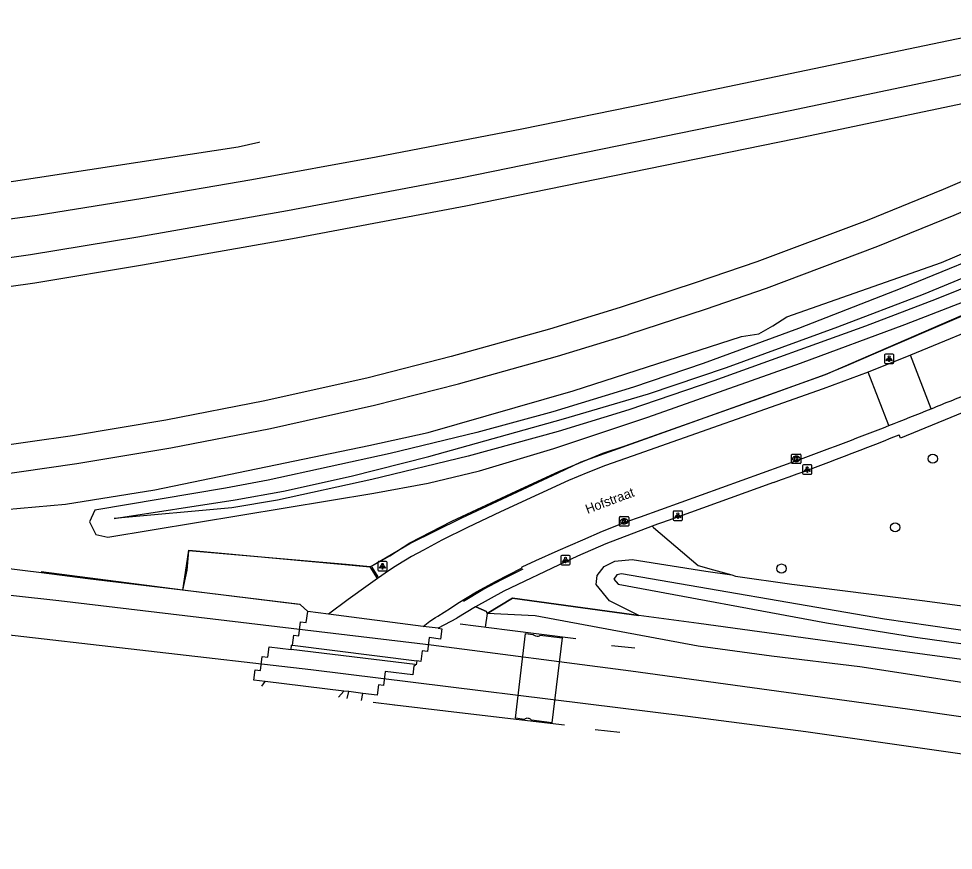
# Model space of a CAD drawing. Extents: x 162990 to 165007, y 383433 to 384336.
# Drawn here: x 163237.1 to 163336.6, y 383947.4 to 384036 of the extents above; entities that cross this region are included whole.
import ezdxf

# ---------------------------------------------------------------- set-up
doc = ezdxf.new("R2010")
doc.units = 0
for name, color, linetype in [('IMGEO_Berm_groen', 7, 'Continuous'), ('IMGEO_Boom', 7, 'Continuous'), ('IMGEO_Grasland_overig', 7, 'Continuous'), ('IMGEO_Greppel_droge_sloot', 7, 'Continuous'), ('IMGEO_Groenvoorziening', 7, 'Continuous'), ('IMGEO_Hek', 7, 'Continuous'), ('IMGEO_Kolk', 7, 'Continuous'), ('IMGEO_Lichtpunt', 7, 'Continuous'), ('IMGEO_Openbare_ruimte_label', 7, 'Continuous'), ('IMGEO_Overweg_gesloten', 7, 'Continuous'), ('IMGEO_Rijbaan_lokaal_open', 7, 'Continuous'), ('IMGEO_Spoor', 7, 'Continuous'), ('IMGEO_Spoorbaan_gesloten', 7, 'Continuous'), ('IMGEO_Spoorbaan_halfverhard', 7, 'Continuous'), ('IMGEO_Voetpad_open', 7, 'Continuous')]:
    doc.layers.add(name, color=color, linetype=linetype)

msp = doc.modelspace()

# ---------------------------------------------------------------- linework, layer by layer
at = {"layer": 'IMGEO_Berm_groen'}
msp.add_lwpolyline([(163274.504, 383977.632), (163278.725, 383980.117), (163284.265, 383982.864), (163294.54, 383987.657), (163296.984, 383988.804), (163323.041, 383998.108), (163383.183, 384024.211), (163402.575, 384035.786), (163402.671, 384035.843), (163402.812, 384035.885), (163403.247, 384036.139), (163416.877, 384040.507), (163432.67, 384043.744)], dxfattribs=at)
at = {"layer": 'IMGEO_Boom'}
for centre in [(163334.456, 383989.158), (163330.444, 383981.843), (163318.336, 383977.453)]:
    msp.add_circle(centre, 0.489, dxfattribs=at)
at = {"layer": 'IMGEO_Grasland_overig'}
for points in [[(163342.972, 384012.156), (163331.165, 384007.304), (163320.164, 384003.038), (163309.979, 383999.286), (163302.567, 383996.776), (163293.987, 383994.145), (163285.879, 383991.937), (163276.631, 383989.703), (163263.65, 383986.875), (163259.094, 383986.022), (163245.152, 383983.669)], [(163245.152, 383983.669), (163244.587, 383982.445), (163245.283, 383981.092), (163246.57, 383980.794), (163274.912, 383985.473), (163280.669, 383986.55), (163286.157, 383987.877), (163294.069, 383990.254), (163304.088, 383993.574), (163320.354, 383999.335), (163331.466, 384003.436), (163338.904, 384006.333)], [(163304.538, 383981.977), (163304.708, 383981.835), (163309.473, 383977.765), (163311.103, 383977.312), (163313.037, 383976.774)], [(163303.12, 383972.457), (163300.026, 383974.011), (163298.586, 383975.747), (163298.705, 383976.708), (163299.453, 383977.67), (163300.569, 383978.245), (163302.435, 383978.402), (163310.274, 383977.162), (163313.037, 383976.774)], [(163286.956, 383972.666), (163289.676, 383974.314), (163297.159, 383973.255), (163303.12, 383972.457)], [(163387.544, 383960.538), (163366.442, 383963.654), (163364.063, 383964.046), (163356.548, 383965.123), (163349.156, 383966.209), (163331.773, 383968.554), (163309.512, 383971.604), (163303.12, 383972.457)]]:
    msp.add_lwpolyline(points, dxfattribs=at)
at = {"layer": 'IMGEO_Greppel_droge_sloot'}
for points in [[(163274.685, 383986.922), (163264.631, 383984.748), (163259.777, 383983.906), (163247.226, 383982.795), (163260.11, 383984.784), (163265.254, 383985.705), (163272.493, 383987.277), (163280.746, 383989.392), (163295.118, 383993.387), (163304.152, 383996.079), (163312.467, 383998.865), (163324.349, 384003.186), (163333.485, 384006.672), (163348.011, 384012.683)], [(163341.944, 384009.015), (163334.832, 384006.165), (163327.28, 384003.289), (163311.133, 383997.456), (163302.073, 383994.345), (163294.531, 383992.039), (163284.935, 383989.436), (163274.685, 383986.922)], [(163409.986, 383960.583), (163388.793, 383964.228), (163377.195, 383965.699), (163360.31, 383968.096), (163346.455, 383969.572), (163329.328, 383972.064), (163301.28, 383976.885), (163300.783, 383976.774), (163300.462, 383976.334), (163300.94, 383975.775), (163323.14, 383971.677), (163332.603, 383970.136), (163384.444, 383962.888), (163409.693, 383958.969)]]:
    msp.add_lwpolyline(points, dxfattribs=at)
at = {"layer": 'IMGEO_Groenvoorziening'}
msp.add_lwpolyline([(163313.037, 383976.774), (163313.451, 383976.659), (163319.434, 383975.788), (163333.339, 383974.06), (163338.947, 383973.319)], dxfattribs=at)
at = {"layer": 'IMGEO_Hek'}
for points in [[(163254.527, 383975.145), (163255.168, 383979.396), (163274.504, 383977.632), (163274.644, 383977.711), (163276.585, 383978.805), (163278.717, 383980.181), (163283.214, 383982.499), (163290.073, 383985.701), (163294.599, 383987.803), (163297.161, 383988.847), (163299.287, 383989.75), (163301.676, 383990.541), (163315.913, 383995.57), (163322.989, 383998.132), (163325.305, 383999.08), (163329.992, 384001.097), (163341.559, 384006.06), (163350.753, 384010.132), (163366.939, 384017.167), (163383.117, 384024.211), (163402.701, 384035.889), (163408.952, 384037.884)], [(163266.956, 383973.642), (163254.527, 383975.145), (163239.451, 383977.111)], [(163274.669, 383977.596), (163275.328, 383976.57)], [(163284.454, 383973.989), (163286.526, 383975.221), (163288.599, 383976.341), (163290.806, 383977.414)], [(163297.159, 383973.255), (163289.676, 383974.314), (163286.956, 383972.666), (163286.758, 383971.22)], [(163285.777, 383973.367), (163286.892, 383972.867)], [(163387.33, 383959.283), (163387.544, 383960.538), (163366.442, 383963.654), (163364.063, 383964.046), (163356.548, 383965.123), (163349.156, 383966.209), (163331.773, 383968.554), (163309.512, 383971.604), (163303.12, 383972.457), (163297.159, 383973.255)], [(163284.096, 383971.554), (163289.091, 383970.927), (163296.413, 383969.999)], [(163300.233, 383969.246), (163302.725, 383969)], [(163274.829, 383963.207), (163277.133, 383962.938), (163285.218, 383961.992), (163295.21, 383960.806)], [(163277.133, 383962.938), (163277.124, 383962.872)], [(163298.477, 383960.317), (163301.101, 383960.028)]]:
    msp.add_lwpolyline(points, dxfattribs=at)
at = {"layer": 'IMGEO_Kolk'}
for p, q in [((163319.412, 383988.714), (163319.412, 383989.566)), ((163319.487, 383989.64), (163320.339, 383989.64)), ((163319.923, 383988.86), (163319.898, 383988.86)), ((163319.9, 383989.42), (163319.925, 383989.42)), ((163320.413, 383989.566), (163320.413, 383988.714)), ((163320.339, 383988.64), (163319.487, 383988.64)), ((163301.06, 383982.057), (163301.06, 383982.909)), ((163301.135, 383982.983), (163301.987, 383982.983)), ((163301.548, 383982.763), (163301.573, 383982.763)), ((163302.061, 383982.909), (163302.061, 383982.057)), ((163301.987, 383981.983), (163301.135, 383981.983)), ((163301.571, 383982.203), (163301.546, 383982.203))]:
    msp.add_line(p, q, dxfattribs=at)
for points in [[(163319.412, 383988.714), (163319.412, 383989.566)], [(163319.487, 383989.64), (163320.339, 383989.64)], [(163319.733, 383989.34), (163319.856, 383989.34), (163319.856, 383989.189), (163319.986, 383989.34), (163320.15, 383989.34), (163320.004, 383989.189), (163320.157, 383988.94), (163320.005, 383988.94), (163319.92, 383989.104), (163319.856, 383989.037), (163319.856, 383988.94), (163319.733, 383988.94), (163319.733, 383989.34)], [(163320.413, 383989.566), (163320.413, 383988.714)], [(163320.339, 383988.64), (163319.487, 383988.64)], [(163301.06, 383982.057), (163301.06, 383982.909)], [(163301.135, 383982.983), (163301.987, 383982.983)], [(163302.061, 383982.909), (163302.061, 383982.057)], [(163301.987, 383981.983), (163301.135, 383981.983)], [(163301.381, 383982.683), (163301.504, 383982.683), (163301.504, 383982.532), (163301.634, 383982.683), (163301.798, 383982.683), (163301.652, 383982.532), (163301.805, 383982.283), (163301.653, 383982.283), (163301.568, 383982.447), (163301.504, 383982.38), (163301.504, 383982.283), (163301.381, 383982.283), (163301.381, 383982.683)]]:
    msp.add_lwpolyline(points, dxfattribs=at)
for centre, start, end in [((163319.489, 383989.564), 91.55205, 178.44795), ((163319.489, 383989.564), 91.55205, 178.44795), ((163320.337, 383989.564), 1.55205, 88.44795), ((163320.337, 383989.564), 1.55205, 88.44795), ((163319.489, 383988.716), 181.55205, 268.44795), ((163319.489, 383988.716), 181.55205, 268.44795), ((163320.337, 383988.716), 271.55205, 358.44795), ((163320.337, 383988.716), 271.55205, 358.44795), ((163301.137, 383982.907), 91.55205, 178.44795), ((163301.137, 383982.907), 91.55205, 178.44795), ((163301.985, 383982.907), 1.55205, 88.44795), ((163301.985, 383982.907), 1.55205, 88.44795), ((163301.137, 383982.059), 181.55205, 268.44795), ((163301.137, 383982.059), 181.55205, 268.44795), ((163301.985, 383982.059), 271.55205, 358.44795), ((163301.985, 383982.059), 271.55205, 358.44795)]:
    msp.add_arc(centre, 0.0765, start, end, dxfattribs=at)
for centre, major_axis, ratio, start_param, end_param in [((163319.899, 383989.14), (-0.387, 0.002), 0.722429, 4.712389, 7.853982), ((163319.924, 383989.14), (-0.39, 0.002), 0.717154, 1.570796, 4.712389), ((163301.547, 383982.483), (-0.387, 0.002), 0.722429, 4.712389, 7.853982), ((163301.572, 383982.483), (-0.39, 0.002), 0.717154, 1.570796, 4.712389)]:
    msp.add_ellipse(centre, major_axis=major_axis, ratio=ratio, start_param=start_param, end_param=end_param, dxfattribs=at)
at = {"layer": 'IMGEO_Lichtpunt'}
for p, q in [((163329.308, 384000.202), (163329.308, 383999.395)), ((163329.308, 384000.202), (163329.308, 383999.395)), ((163330.21, 384000.297), (163329.402, 384000.297)), ((163330.21, 384000.297), (163329.402, 384000.297)), ((163330.304, 383999.395), (163330.304, 384000.202)), ((163330.304, 383999.395), (163330.304, 384000.202)), ((163329.402, 383999.301), (163330.21, 383999.301)), ((163329.402, 383999.301), (163330.21, 383999.301)), ((163320.582, 383988.407), (163320.582, 383987.6)), ((163320.582, 383988.407), (163320.582, 383987.6)), ((163321.484, 383988.502), (163320.676, 383988.502)), ((163321.484, 383988.502), (163320.676, 383988.502)), ((163321.578, 383987.6), (163321.578, 383988.407)), ((163321.578, 383987.6), (163321.578, 383988.407)), ((163320.676, 383987.506), (163321.484, 383987.506)), ((163320.676, 383987.506), (163321.484, 383987.506)), ((163306.797, 383983.488), (163306.797, 383982.681)), ((163306.797, 383983.488), (163306.797, 383982.681)), ((163307.699, 383983.583), (163306.891, 383983.583)), ((163307.699, 383983.583), (163306.891, 383983.583)), ((163307.793, 383982.681), (163307.793, 383983.488)), ((163307.793, 383982.681), (163307.793, 383983.488)), ((163306.891, 383982.587), (163307.699, 383982.587)), ((163306.891, 383982.587), (163307.699, 383982.587)), ((163295.727, 383978.851), (163294.919, 383978.851)), ((163295.727, 383978.851), (163294.919, 383978.851)), ((163275.317, 383978.111), (163275.317, 383977.304)), ((163275.317, 383978.111), (163275.317, 383977.304)), ((163276.219, 383978.206), (163275.411, 383978.206)), ((163276.219, 383978.206), (163275.411, 383978.206)), ((163276.313, 383977.304), (163276.313, 383978.111)), ((163276.313, 383977.304), (163276.313, 383978.111)), ((163294.825, 383978.756), (163294.825, 383977.949)), ((163294.825, 383978.756), (163294.825, 383977.949)), ((163294.919, 383977.855), (163295.727, 383977.855)), ((163294.919, 383977.855), (163295.727, 383977.855)), ((163295.821, 383977.949), (163295.821, 383978.756)), ((163295.821, 383977.949), (163295.821, 383978.756)), ((163275.411, 383977.21), (163276.219, 383977.21)), ((163275.411, 383977.21), (163276.219, 383977.21))]:
    msp.add_line(p, q, dxfattribs=at)
for points in [[(163329.682, 383999.866), (163329.721, 383999.838), (163329.533, 383999.576), (163329.495, 383999.603), (163329.682, 383999.866)], [(163329.784, 383999.818), (163329.831, 383999.818), (163329.831, 383999.496), (163329.784, 383999.496), (163329.784, 383999.818)], [(163329.894, 383999.838), (163329.932, 383999.865), (163330.119, 383999.603), (163330.08, 383999.575), (163329.894, 383999.838)], [(163320.956, 383988.071), (163320.995, 383988.043), (163320.807, 383987.781), (163320.769, 383987.808), (163320.956, 383988.071)], [(163321.058, 383988.023), (163321.105, 383988.023), (163321.105, 383987.701), (163321.058, 383987.701), (163321.058, 383988.023)], [(163321.168, 383988.043), (163321.206, 383988.07), (163321.393, 383987.808), (163321.354, 383987.78), (163321.168, 383988.043)], [(163307.171, 383983.152), (163307.21, 383983.124), (163307.022, 383982.862), (163306.984, 383982.889), (163307.171, 383983.152)], [(163307.273, 383983.104), (163307.32, 383983.104), (163307.32, 383982.782), (163307.273, 383982.782), (163307.273, 383983.104)], [(163307.383, 383983.124), (163307.421, 383983.151), (163307.608, 383982.889), (163307.569, 383982.861), (163307.383, 383983.124)], [(163275.691, 383977.775), (163275.73, 383977.747), (163275.542, 383977.485), (163275.504, 383977.512), (163275.691, 383977.775)], [(163275.903, 383977.747), (163275.941, 383977.774), (163276.128, 383977.512), (163276.089, 383977.484), (163275.903, 383977.747)], [(163295.199, 383978.42), (163295.238, 383978.392), (163295.05, 383978.13), (163295.012, 383978.157), (163295.199, 383978.42)], [(163295.301, 383978.372), (163295.348, 383978.372), (163295.348, 383978.05), (163295.301, 383978.05), (163295.301, 383978.372)], [(163295.411, 383978.392), (163295.449, 383978.419), (163295.636, 383978.157), (163295.597, 383978.129), (163295.411, 383978.392)], [(163275.793, 383977.727), (163275.84, 383977.727), (163275.84, 383977.405), (163275.793, 383977.405), (163275.793, 383977.727)]]:
    msp.add_lwpolyline(points, dxfattribs=at)
for centre in [(163329.807, 384000), (163321.081, 383988.205), (163307.296, 383983.286), (163275.816, 383977.909), (163295.324, 383978.554)]:
    msp.add_circle(centre, 0.0994, dxfattribs=at)
for centre, start, end in [((163329.402, 384000.202), 90, 180), ((163329.402, 384000.202), 90, 180), ((163330.21, 384000.202), 0, 90), ((163330.21, 384000.202), 0, 90), ((163329.402, 383999.395), 180, 270), ((163329.402, 383999.395), 180, 270), ((163330.21, 383999.395), 270, 0), ((163330.21, 383999.395), 270, 360), ((163320.676, 383988.407), 90, 180), ((163320.676, 383988.407), 90, 180), ((163321.484, 383988.407), 0, 90), ((163321.484, 383988.407), 0, 90), ((163320.676, 383987.6), 180, 270), ((163320.676, 383987.6), 180, 270), ((163321.484, 383987.6), 270, 0), ((163321.484, 383987.6), 270, 360), ((163306.891, 383983.488), 90, 180), ((163306.891, 383983.488), 90, 180), ((163307.699, 383983.488), 0, 90), ((163307.699, 383983.488), 0, 90), ((163306.891, 383982.681), 180, 270), ((163306.891, 383982.681), 180, 270), ((163307.699, 383982.681), 270, 0), ((163307.699, 383982.681), 270, 360), ((163294.919, 383978.756), 90, 180), ((163294.919, 383978.756), 90, 180), ((163295.727, 383978.756), 0, 90), ((163295.727, 383978.756), 0, 90), ((163275.411, 383978.111), 90, 180), ((163275.411, 383978.111), 90, 180), ((163276.219, 383978.111), 0, 90), ((163276.219, 383978.111), 0, 90), ((163294.919, 383977.949), 180, 270), ((163294.919, 383977.949), 180, 270), ((163295.727, 383977.949), 270, 0), ((163295.727, 383977.949), 270, 360), ((163275.411, 383977.304), 180, 270), ((163275.411, 383977.304), 180, 270), ((163276.219, 383977.304), 270, 0), ((163276.219, 383977.304), 270, 360)]:
    msp.add_arc(centre, 0.0946, start, end, dxfattribs=at)
at = {"layer": 'IMGEO_Overweg_gesloten'}
for points in [[(163266.223, 383969.281), (163266.357, 383970.366), (163266.911, 383970.298), (163267.095, 383971.787), (163267.702, 383971.712), (163267.85, 383972.865)], [(163270.07, 383972.581), (163267.85, 383972.865)], [(163280.155, 383971.294), (163270.07, 383972.581)], [(163281.743, 383971.091), (163282.132, 383971.041), (163281.998, 383969.948), (163280.806, 383970.095), (163280.623, 383968.607), (163280.034, 383968.679), (163279.896, 383967.556), (163279.464, 383967.61)], [(163281.743, 383971.091), (163280.155, 383971.294)], [(163263.311, 383965.418), (163262.124, 383965.562), (163262.256, 383966.656), (163262.824, 383966.588), (163263.003, 383968.077), (163263.598, 383968.006), (163263.732, 383969.12), (163266.077, 383968.834)], [(163279.299, 383967.218), (163266.077, 383968.834)], [(163266.223, 383969.281), (163279.464, 383967.61)], [(163279.299, 383967.218), (163279.283, 383967.091), (163279.176, 383967.104), (163279.061, 383966.15), (163276.121, 383966.503), (163275.942, 383965.014), (163275.381, 383965.081), (163275.247, 383963.975), (163273.715, 383964.16)], [(163271.683, 383964.406), (163263.311, 383965.418)], [(163272.219, 383964.341), (163271.683, 383964.406)], [(163273.715, 383964.16), (163272.219, 383964.341)]]:
    msp.add_lwpolyline(points, dxfattribs=at)
at = {"layer": 'IMGEO_Rijbaan_lokaal_open'}
for points in [[(163364.723, 384014.183), (163349.325, 384007.457), (163341.556, 384004.085), (163332.067, 384000.185)], [(163332.067, 384000.185), (163327.564, 383998.356)], [(163334.277, 383994.471), (163332.067, 384000.185)], [(163327.564, 383998.356), (163322.766, 383996.61), (163302.414, 383989.419), (163299.572, 383988.415), (163297.702, 383987.696), (163295.645, 383986.817), (163292.488, 383985.394), (163288.397, 383983.488), (163284.88, 383981.84), (163282.128, 383980.477), (163280.177, 383979.402), (163278.915, 383978.721), (163277.447, 383977.863), (163277.156, 383977.674), (163276.568, 383977.292), (163275.296, 383976.404)], [(163329.76, 383992.677), (163327.564, 383998.356)], [(163280.155, 383971.294), (163280.846, 383971.835), (163281.46, 383972.231), (163281.717, 383972.396), (163283.075, 383973.248), (163283.852, 383973.763), (163285.829, 383974.963), (163287.921, 383976.127), (163290.63, 383977.508), (163290.699, 383977.621), (163292.173, 383978.312), (163294.536, 383979.378), (163297.17, 383980.528), (163299.265, 383981.44), (163301.863, 383982.449), (163303.301, 383982.956), (163320.649, 383989.228)], [(163274.504, 383977.632), (163271.951, 383977.87), (163269.445, 383978.093), (163255.162, 383979.353), (163254.956, 383977.287), (163254.51, 383975.136)], [(163275.296, 383976.404), (163274.504, 383977.632)], [(163275.296, 383976.404), (163274.286, 383975.698), (163272.178, 383974.143), (163270.07, 383972.581)], [(163271.683, 383964.406), (163271.115, 383963.746)]]:
    msp.add_lwpolyline(points, dxfattribs=at)
for centre, radius, start, end in [((163168.64, 384405.397), 443.053, 291.95353, 292.59596), ((163164.319, 384415.815), 454.331, 291.35484, 291.96777), ((163165.37, 384413.176), 451.49, 290.11617, 291.35249)]:
    msp.add_arc(centre, radius, start, end, dxfattribs=at)
at = {"layer": 'IMGEO_Spoor'}
for points in [[(163482.504, 384064.124), (163438.347, 384055.003), (163304.284, 384027.02), (163290.651, 384024.258), (163275.14, 384021.273), (163261.909, 384018.846), (163250.276, 384016.868), (163239.034, 384015.076), (163225.051, 384013.191), (163210.675, 384011.424), (163197.565, 384010.035), (163186.306, 384009.051), (163170.778, 384007.955), (163157.742, 384007.242), (163145.353, 384006.773), (163136.4, 384006.585), (163127.534, 384006.532), (163114.97, 384006.669), (163093.304, 384007.27), (163079.785, 384007.903), (163066.124, 384008.71), (163050.352, 384009.854), (163020.285, 384012.339), (163007.925, 384013.445)], [(163407.712, 384044.788), (163319.259, 384026.2), (163284.13, 384019.05), (163265.686, 384015.557), (163249.751, 384012.76), (163238.315, 384010.853), (163218.995, 384008.118), (163175.893, 384003.972), (163154.95, 384002.739), (163133.868, 384002.083), (163105.006, 384002.112), (163077.274, 384002.797), (163012.331, 384005.282)], [(163408.318, 384042.866), (163400.768, 384040.461), (163393.355, 384037.964), (163386.355, 384035.481), (163379.622, 384032.97), (163369.229, 384028.838), (163351.977, 384021.599), (163336.715, 384015.07), (163328.559, 384011.745), (163316.709, 384007.296), (163310.206, 384005.061), (163302.041, 384002.4)], [(163171.029, 383983.535), (163183.994, 383983.622), (163194.126, 383983.904), (163202.816, 383984.295), (163211.591, 383984.954), (163223, 383986.029), (163234.105, 383987.344), (163243.254, 383988.629), (163253.264, 383990.312), (163263.9, 383992.378), (163274.976, 383994.865), (163283.901, 383997.126), (163294.45, 384000.073), (163302.041, 384002.4)], [(163201.068, 383978.5), (163241.346, 383974.044), (163280.995, 383969.314), (163302.293, 383966.549), (163331.756, 383962.529), (163375.788, 383956.21), (163396.784, 383952.981), (163406.788, 383951.295)], [(163233.552, 383970.681), (163268.173, 383966.7), (163308.347, 383961.743), (163320.922, 383960.101), (163364.427, 383953.887), (163378.978, 383951.698), (163406.172, 383947.444)]]:
    msp.add_lwpolyline(points, dxfattribs=at)
at = {"layer": 'IMGEO_Spoorbaan_gesloten'}
msp.add_lwpolyline([(163291.069, 383970.536), (163291.869, 383970.442), (163291.993, 383970.345), (163292.133, 383970.28), (163292.317, 383970.256), (163292.457, 383970.264), (163292.548, 383970.29), (163292.638, 383970.351), (163294.975, 383970.075), (163293.879, 383961.035), (163291.686, 383961.298), (163291.657, 383961.339), (163291.577, 383961.408), (163291.45, 383961.472), (163291.353, 383961.494), (163291.213, 383961.503), (163291.116, 383961.487), (163291.007, 383961.434), (163290.951, 383961.386), (163289.983, 383961.502), (163291.069, 383970.536)], dxfattribs=at)
at = {"layer": 'IMGEO_Spoorbaan_halfverhard'}
for points in [[(163230.824, 383983.328), (163242.036, 383984.311), (163251.576, 383985.84), (163274.361, 383990.577), (163280.675, 383991.959), (163296.124, 383996.4), (163314.071, 384002.164), (163315.928, 384002.462), (163317.416, 384003.302), (163318.906, 384004.275), (163335.392, 384010.064), (163360.951, 384020.902), (163385.565, 384031.616), (163387.408, 384031.711), (163388.822, 384032.318), (163390.428, 384033.418), (163407.515, 384038.818), (163419.45, 384042.131), (163441.356, 384047.511)], [(163219.349, 384005.138), (163238.772, 384007.888), (163250.257, 384009.803), (163266.224, 384012.606), (163284.708, 384016.106), (163319.867, 384023.262), (163376.601, 384035.185), (163350.807, 384024.361), (163335.559, 384017.838), (163327.465, 384014.539), (163315.694, 384010.119), (163309.254, 384007.906), (163301.137, 384005.261), (163293.607, 384002.952), (163283.129, 384000.025), (163274.279, 383997.783), (163263.285, 383995.315), (163252.729, 383993.264), (163242.797, 383991.594), (163233.72, 383990.319)], [(163262.721, 384022.903), (163262.634, 384022.847), (163260.436, 384022.321), (163233.895, 384018.308)], [(163254.51, 383975.136), (163244.435, 383976.35), (163239.472, 383977.013), (163221.251, 383979.238)], [(163267.85, 383972.865), (163267.045, 383973.626), (163254.51, 383975.136)], [(163285.728, 383973.389), (163283.75, 383972.183), (163283.694, 383972.14), (163281.743, 383971.091)], [(163286.956, 383972.666), (163286.892, 383972.867), (163285.777, 383973.367), (163285.728, 383973.389)], [(163387.33, 383959.283), (163386.235, 383959.144), (163385.125, 383958.855), (163383.132, 383958.867), (163373.017, 383960.193), (163354.264, 383963.185), (163346.802, 383964.755), (163338.923, 383965.101), (163326.694, 383966.98), (163317.279, 383968.124), (163309.461, 383969.198), (163292.074, 383972.407), (163286.956, 383972.666)], [(163266.077, 383968.834), (163266.133, 383969.292), (163266.223, 383969.281)], [(163279.464, 383967.61), (163279.413, 383967.204), (163279.299, 383967.218)], [(163262.963, 383964.931), (163263.311, 383965.418)], [(163273.565, 383963.39), (163273.715, 383964.16)]]:
    msp.add_lwpolyline(points, dxfattribs=at)
at = {"layer": 'IMGEO_Voetpad_open'}
for points in [[(163343.72, 383996.556), (163331.019, 383991.354), (163330.869, 383991.697)], [(163317.484, 383986.621), (163306.957, 383982.806)], [(163304.538, 383981.977), (163299.601, 383980.078), (163296.589, 383978.775), (163295.328, 383978.175), (163288.735, 383975.055), (163285.728, 383973.389)], [(163272.059, 383963.608), (163272.219, 383964.341)]]:
    msp.add_lwpolyline(points, dxfattribs=at)
for centre, radius, start, end in [((163185.239, 384355.525), 391.892, 289.72173, 291.81477), ((163339.265, 383884.588), 103.395, 108.20825, 109.62529)]:
    msp.add_arc(centre, radius, start, end, dxfattribs=at)

# ---------------------------------------------------------------- texts
at = {"layer": 'IMGEO_Openbare_ruimte_label'}
msp.add_text('Hofstraat', height=1, rotation=20.55605, dxfattribs=at).set_placement((163297.663, 383983.273))

doc.saveas('drawing.dxf')
